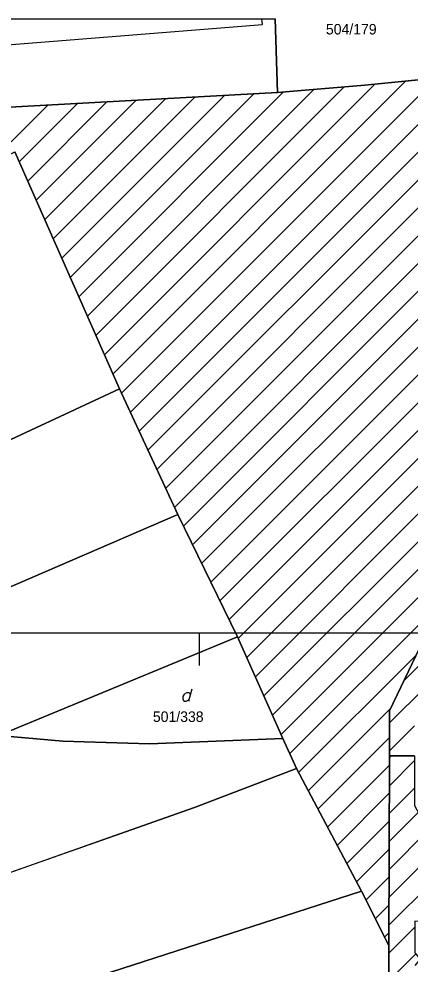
# Model space of a CAD drawing. Extents: x -264309 to -263505, y -1242443 to -1241763.
# Drawn here: x -264133.4 to -264073.7, y -1242101 to -1241957 of the extents above; entities that cross this region are included whole.
import ezdxf

# ---------------------------------------------------------------- set-up
doc = ezdxf.new("R2010")
doc.units = 0
for name, color, linetype in [('KN_2019_08_16_KLADPAR', 7, 'Continuous'), ('KN_2019_08_16_ZAPPAR', 7, 'Continuous'), ('RAM_NA_TLAC_10xA4_1-500', 7, 'Continuous'), ('SRAFY_PARCELY', 7, 'Continuous')]:
    doc.layers.add(name, color=color, linetype=linetype)

msp = doc.modelspace()

# ---------------------------------------------------------------- linework, layer by layer
at = {"layer": 'KN_2019_08_16_KLADPAR'}
for p, q in [((-264200.28, -1241956.96), (-264094.27, -1241956.96)), ((-264094.27, -1241956.96), (-264093.88, -1241968.2)), ((-264080.59, -1241967.06), (-264013.93, -1241960.42)), ((-264093.88, -1241968.2), (-264080.59, -1241967.06)), ((-264093.88, -1241968.2), (-264199.33, -1241973.87)), ((-264199.33, -1241973.87), (-264093.88, -1241968.2)), ((-264118.01, -1242013.33), (-264133.98, -1241977.23)), ((-264109.13, -1242032.5), (-264118.01, -1242013.33)), ((-264100, -1242051.16), (-264109.13, -1242032.5)), ((-264093.07, -1242066.63), (-264100, -1242051.16)), ((-264071.64, -1242051.59), (-264076.8, -1242062.43)), ((-264107.18, -1242059.97), (-264106.91, -1242059.07)), ((-264076.8, -1242062.43), (-264076.82, -1242069.31)), ((-264091, -1242071.24), (-264093.07, -1242066.63)), ((-264076.82, -1242069.31), (-264076.9, -1242098.2)), ((-264106.54, -1242077.18), (-264091, -1242071.24)), ((-264081.08, -1242089.93), (-264091, -1242071.24)), ((-264091, -1242071.24), (-264081.08, -1242089.93)), ((-264118.83, -1242081.48), (-264106.54, -1242077.18)), ((-264143.3, -1242090.1), (-264118.83, -1242081.48)), ((-264081.08, -1242089.93), (-264120.91, -1242102.78)), ((-264076.9, -1242098.2), (-264081.08, -1242089.93))]:
    msp.add_line(p, q, dxfattribs=at)
for points in [[(-264080.59, -1241967.06), (-264093.88, -1241968.2), (-264094.27, -1241956.96)], [(-264013.95, -1241956.96), (-264013.93, -1241960.42), (-264080.59, -1241967.06)], [(-264073, -1242069.31), (-264076.82, -1242069.31), (-264076.8, -1242062.43), (-264071.64, -1242051.59)], [(-264107.36, -1242060.96), (-264107.36, -1242060.69), (-264107.18, -1242059.97), (-264107.27, -1242059.79), (-264107.45, -1242059.7), (-264107.72, -1242059.7), (-264107.99, -1242059.79), (-264108.17, -1242059.97), (-264108.35, -1242060.24), (-264108.35, -1242060.6), (-264108.26, -1242060.87), (-264108.08, -1242060.96), (-264107.81, -1242060.96), (-264107.63, -1242060.87), (-264107.36, -1242060.69)], [(-264076.93, -1242111.1), (-264076.9, -1242098.2), (-264076.82, -1242069.31), (-264073, -1242069.31), (-264072.99, -1242076.85), (-264070.77, -1242081.01), (-264065.29, -1242082.03), (-264063.05, -1242082.02), (-264063.02, -1242088.27), (-264065.59, -1242088.27), (-264068.16, -1242088.59), (-264070.53, -1242091.66), (-264070.93, -1242094.55), (-264072.96, -1242094.5), (-264072.96, -1242099.3), (-264072.11, -1242100.28), (-264072.96, -1242101.25)]]:
    msp.add_lwpolyline(points, dxfattribs=at)
for points in [[(-264184.63, -1242044.36), (-264189.98, -1242046.97), (-264197.18, -1242041.92), (-264203.38, -1242036.91), (-264207.78, -1242033.03), (-264215.63, -1242024.82), (-264219.93, -1242019.72), (-264203.29, -1242011.27), (-264198.58, -1242008.96), (-264197.33, -1242008.76), (-264194.98, -1242008.87), (-264193.09, -1242009.32), (-264190.87, -1242010.33), (-264189.65, -1242011.32), (-264193.93, -1242006.68), (-264133.98, -1241977.23), (-264118.01, -1242013.33), (-264147.41, -1242027.03), (-264155.75, -1242030.57)], [(-264189.98, -1242046.97), (-264184.63, -1242044.36), (-264155.75, -1242030.57), (-264147.41, -1242027.03), (-264118.01, -1242013.33), (-264109.13, -1242032.5), (-264168.01, -1242057.92), (-264173.43, -1242055.54), (-264181.27, -1242051.82)], [(-264109.13, -1242032.5), (-264100, -1242051.16), (-264136.47, -1242066.18), (-264141.87, -1242065.13), (-264148.68, -1242063.74), (-264155.45, -1242062), (-264161.74, -1242060.05), (-264168.01, -1242057.92)], [(-264126.66, -1242067.07), (-264136.47, -1242066.18), (-264100, -1242051.16), (-264093.07, -1242066.63), (-264113.43, -1242067.44)], [(-264136.47, -1242066.18), (-264126.66, -1242067.07), (-264113.43, -1242067.44), (-264093.07, -1242066.63), (-264091, -1242071.24), (-264106.54, -1242077.18), (-264118.83, -1242081.48), (-264143.3, -1242090.1), (-264171.23, -1242099.67), (-264195.32, -1242108.83), (-264231.66, -1242125.67), (-264256.42, -1242138.67), (-264258.61, -1242135.22), (-264265.78, -1242123.95), (-264240.95, -1242110.43), (-264231.21, -1242105.15), (-264197.75, -1242090.71), (-264182.59, -1242084.17), (-264140.89, -1242068)], [(-264246.81, -1242153.57), (-264207.96, -1242133.21), (-264176.83, -1242121.28), (-264120.91, -1242102.78), (-264081.08, -1242089.93), (-264076.9, -1242098.2), (-264076.93, -1242111.1), (-264102.41, -1242118.92), (-264128.45, -1242126.51), (-264158.28, -1242134.19), (-264188.56, -1242145.27), (-264215.11, -1242156.51), (-264222.8, -1242159.81), (-264237.43, -1242168.42)]]:
    msp.add_lwpolyline(points, close=True, dxfattribs=at)
at = {"layer": 'KN_2019_08_16_ZAPPAR'}
msp.add_lwpolyline([(-264190.63, -1241965.35), (-264096.18, -1241957.82), (-264096.28, -1241956.96)], dxfattribs=at)
at = {"layer": 'RAM_NA_TLAC_10xA4_1-500'}
msp.add_line((-264105.83, -1242050.54), (-264105.83, -1242055.54), dxfattribs=at)
msp.add_lwpolyline([(-264210.83, -1242050.54), (-264105.83, -1242050.54), (-264000.83, -1242050.54), (-263895.83, -1242050.54), (-263790.83, -1242050.54), (-263685.83, -1242050.54), (-263685.83, -1242199.04), (-263685.83, -1242347.54), (-263790.83, -1242347.54), (-263895.83, -1242347.54), (-264000.83, -1242347.54), (-264105.83, -1242347.54), (-264210.83, -1242347.54), (-264210.83, -1242199.04)], close=True, dxfattribs=at)
at = {"layer": 'SRAFY_PARCELY'}
for p, q in [((-264101.29, -1242048.53), (-264013.1, -1241960.34)), ((-264105.47, -1242039.98), (-264027.23, -1241961.75)), ((-264104.08, -1242042.83), (-264022.52, -1241961.28)), ((-264102.68, -1242045.68), (-264017.81, -1241960.81)), ((-264109.63, -1242031.42), (-264041.37, -1241963.15)), ((-264108.26, -1242034.28), (-264036.66, -1241962.68)), ((-264106.86, -1242037.13), (-264031.95, -1241962.21)), ((-264113.66, -1242022.72), (-264055.51, -1241964.56)), ((-264112.32, -1242025.62), (-264050.79, -1241964.09)), ((-264110.98, -1242028.52), (-264046.08, -1241963.62)), ((-264117.69, -1242014.02), (-264069.64, -1241965.97)), ((-264116.35, -1242016.92), (-264064.93, -1241965.5)), ((-264115, -1242019.82), (-264060.22, -1241965.03)), ((-264099.9, -1242051.38), (-264014.12, -1241965.6)), ((-264122.91, -1242002.26), (-264088.37, -1241967.73)), ((-264121.6, -1242005.2), (-264083.73, -1241967.33)), ((-264120.3, -1242008.15), (-264079.07, -1241966.91)), ((-264119, -1242011.09), (-264074.35, -1241966.44)), ((-264129.41, -1241987.56), (-264110.97, -1241969.12)), ((-264128.11, -1241990.5), (-264106.49, -1241968.88)), ((-264126.81, -1241993.44), (-264102.01, -1241968.64)), ((-264125.51, -1241996.38), (-264097.52, -1241968.4)), ((-264124.21, -1241999.32), (-264093.01, -1241968.13)), ((-264134.54, -1241975.71), (-264128.91, -1241970.08)), ((-264133.32, -1241978.73), (-264124.43, -1241969.84)), ((-264132.01, -1241981.67), (-264119.94, -1241969.6)), ((-264130.71, -1241984.61), (-264115.46, -1241969.36)), ((-264098.59, -1242054.31), (-264014.11, -1241969.83)), ((-264097.28, -1242057.24), (-264014.1, -1241974.07)), ((-264095.96, -1242060.17), (-264014.09, -1241978.3)), ((-264094.65, -1242063.1), (-264014.09, -1241982.54)), ((-264093.34, -1242066.03), (-264014.08, -1241986.77)), ((-264092.02, -1242068.96), (-264014.07, -1241991.01)), ((-264074.61, -1242057.84), (-264066.17, -1242049.39)), ((-264090.67, -1242071.85), (-264072.76, -1242053.94)), ((-264076.81, -1242064.27), (-264071.23, -1242058.7)), ((-264089.2, -1242074.63), (-264076.61, -1242062.04)), ((-264076.82, -1242068.53), (-264073.01, -1242064.72)), ((-264087.73, -1242077.4), (-264076.81, -1242066.48)), ((-264076.83, -1242073.84), (-264073, -1242070)), ((-264076.82, -1242069.58), (-264076.55, -1242069.31)), ((-264086.26, -1242080.17), (-264076.82, -1242070.73)), ((-264076.84, -1242078.09), (-264072.99, -1242074.24)), ((-264084.79, -1242082.94), (-264076.84, -1242074.99)), ((-264076.86, -1242082.34), (-264072.42, -1242077.91)), ((-264083.32, -1242085.71), (-264076.85, -1242079.24)), ((-264076.88, -1242090.85), (-264067.62, -1242081.6)), ((-264076.87, -1242086.6), (-264070.95, -1242080.68)), ((-264076.89, -1242095.11), (-264063.81, -1242082.02)), ((-264081.85, -1242088.48), (-264076.86, -1242083.5)), ((-264080.4, -1242091.28), (-264076.87, -1242087.75)), ((-264078.97, -1242094.1), (-264076.88, -1242092.01)), ((-264076.9, -1242099.36), (-264072.96, -1242095.42)), ((-264077.55, -1242096.91), (-264076.89, -1242096.26)), ((-264076.91, -1242103.61), (-264072.79, -1242099.49))]:
    msp.add_line(p, q, dxfattribs=at)

# ---------------------------------------------------------------- texts
at = {"layer": 'KN_2019_08_16_KLADPAR'}
for s, p in [('504/179', (-264086.51, -1241959.33)), ('501/338', (-264112.91, -1242064.12))]:
    msp.add_text(s, height=1.6, dxfattribs=at).set_placement(p)

doc.saveas('drawing.dxf')
